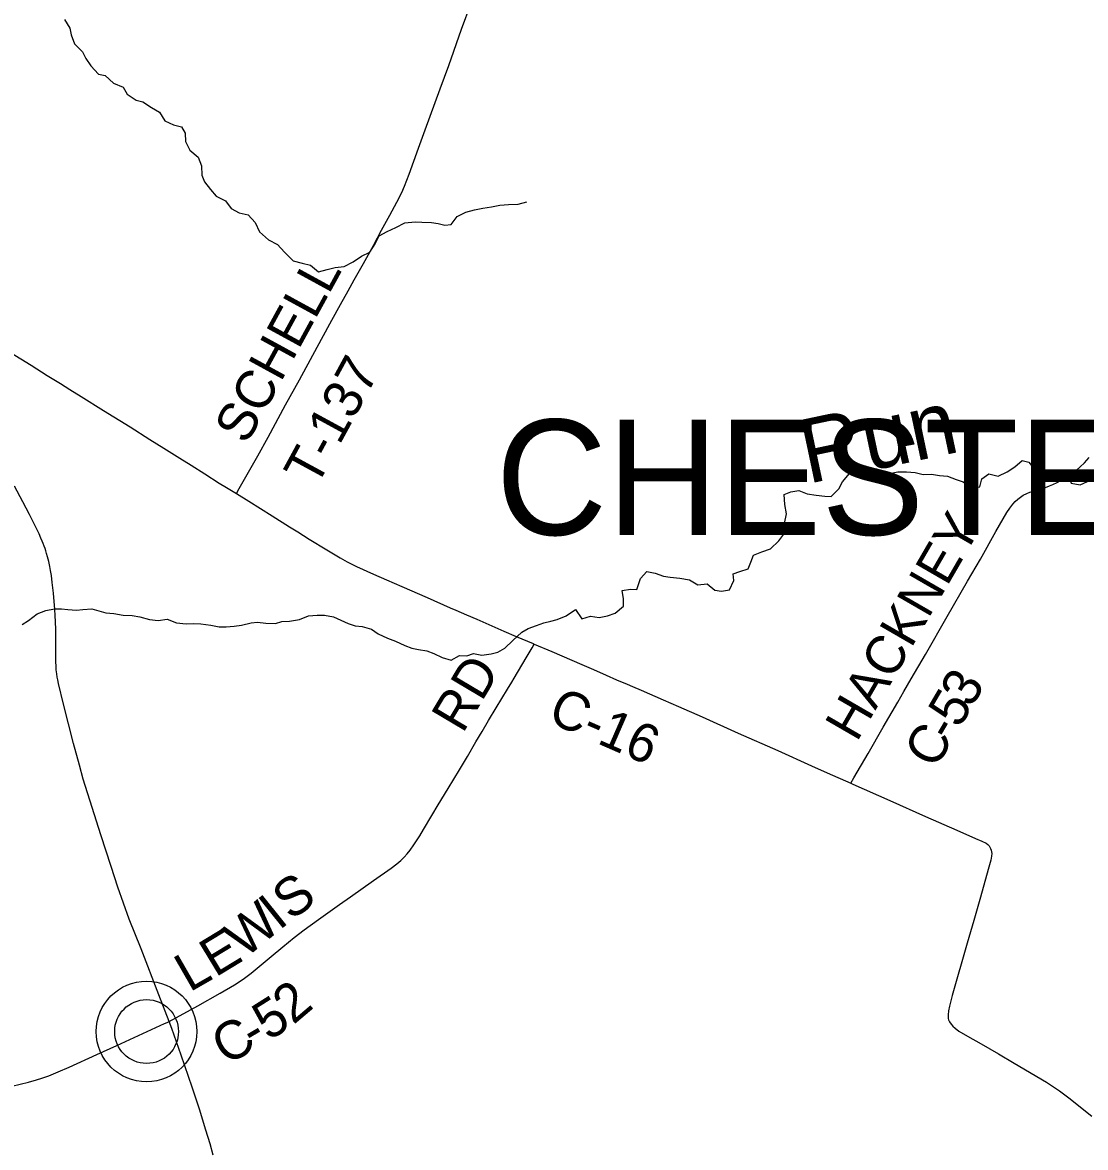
# Model space of a CAD drawing. Extents: x 1442749 to 1756758, y 235267 to 677782.
# Drawn here: x 1560414 to 1568709, y 552520 to 561298 of the extents above; entities that cross this region are included whole.
import ezdxf

# ---------------------------------------------------------------- set-up
doc = ezdxf.new("R2010")
doc.units = 0
for name, color, linetype in [('GM_X_County_Road', 7, 'Continuous'), ('GM_X_County_Road_Text', 7, 'Continuous'), ('GM_X_Minor_River', 7, 'Continuous'), ('GM_X_Minor_River_Text', 7, 'Continuous'), ('GM_X_State_Route', 7, 'Continuous'), ('GM_X_Township_Road', 7, 'Continuous'), ('GM_X_Township_Road_Text', 7, 'Continuous'), ('GM_X_Township_Text', 7, 'Continuous'), ('GM_X_Unincorporated', 7, 'Continuous'), ('GM_X_Unincorporated_Location', 7, 'Continuous')]:
    doc.layers.add(name, color=color, linetype=linetype)

msp = doc.modelspace()

# ---------------------------------------------------------------- linework, layer by layer
at = {"layer": 'GM_X_County_Road'}
for points in [[(1559644.9, 559141.5), (1559858.5, 559011.6), (1559997.1, 558924), (1560206.4, 558794.6), (1560320.7, 558723.8), (1560482.5, 558623.7), (1560607.3, 558544.8), (1560710.3, 558480.9), (1560782.6, 558435.8), (1560871.4, 558379.8), (1561046.9, 558270.7), (1561253.1, 558142.9), (1561408.2, 558044.6), (1561516.6, 557976.6), (1561642, 557898.8), (1561731.1, 557843.3), (1561836.3, 557776.5), (1561949.5, 557703.9), (1562005.6, 557669.8), (1562083.2, 557622.2)], [(1566877, 555363), (1566901.9, 555405.2), (1567013.3, 555594.3), (1567131.1, 555799.1), (1567244.3, 555995), (1567292.2, 556077.2), (1567349.4, 556176.8), (1567460.1, 556366.7), (1567629.7, 556662.8), (1567789.2, 556938), (1567889.4, 557111.3), (1568010.5, 557325.4), (1568095.7, 557473.5), (1568118.8, 557509.6), (1568141.1, 557538.6), (1568161, 557560.9), (1568180.5, 557579.2), (1568201.5, 557595.6), (1568224.2, 557609.7), (1568251.1, 557623), (1568276, 557632.6), (1568338.9, 557652.1), (1568398.1, 557670.6), (1568428.7, 557681.8), (1568455.7, 557693), (1568487.9, 557708.5), (1568530.9, 557731.9), (1568564.6, 557751.7), (1568605.3, 557778.9), (1568636.5, 557802.5), (1568668.6, 557830), (1568701, 557862.1), (1568737.9, 557903.4)], [(1562083.2, 557622.2), (1562181.7, 557561.9), (1562270.9, 557506.7), (1562362.1, 557448.4), (1562497.8, 557362.5), (1562561.8, 557322.6), (1562651.1, 557267.4), (1562787.9, 557183.5), (1562891.9, 557120.8), (1562946.5, 557090.4), (1563020, 557053.6), (1563154.3, 556992.4), (1563253.5, 556949.1), (1563374, 556897.3), (1563572.4, 556810.7), (1563752.8, 556731.8), (1563795.1, 556713.9), (1563879.2, 556677.4), (1563960, 556641.3), (1564170.5, 556549.4), (1564266.9, 556507.6), (1564399.8, 556451.8), (1564407.6, 556448.5)], [(1561559.1, 553502.2), (1561782.9, 553625.7), (1561957.4, 553723.7), (1562067.6, 553788.3), (1562098.1, 553807.5), (1562146.2, 553841.3), (1562198.4, 553880.7), (1562246.7, 553920), (1562354.9, 554010.4), (1562445.3, 554086.6), (1562534.7, 554158.8), (1562613.1, 554218.6), (1562724.7, 554299.6), (1562887.7, 554415.7), (1562973.2, 554476.7), (1563153.1, 554603.2), (1563290.1, 554699.2), (1563334.5, 554732.6), (1563366.9, 554759.9), (1563392.7, 554784.6), (1563416.9, 554810.9), (1563439.2, 554838.9), (1563469.1, 554881.7), (1563515.8, 554952.9), (1563544.6, 555000.5), (1563609.4, 555110.6), (1563657.8, 555192.5), (1563734.8, 555322.2), (1563823.6, 555467.8), (1563885.9, 555571.8), (1563952.4, 555684.7), (1564000.9, 555766.6), (1564051.8, 555851), (1564111, 555949.3), (1564199, 556095.3), (1564232.2, 556151.8), (1564250.6, 556182.9), (1564343.9, 556341.1), (1564390.8, 556420), (1564407.6, 556448.5)], [(1564407.6, 556448.5), (1564544.6, 556390.2), (1564779.4, 556288.7), (1564869.5, 556249.3), (1564968.7, 556206), (1565049.7, 556170.2), (1565134, 556134), (1565173.4, 556117.5), (1565242.8, 556088.1), (1565413.6, 556012.4), (1565533.8, 555959.7), (1565717, 555879.1), (1565998.4, 555753.2), (1566307.4, 555616.6), (1566570.8, 555498.4), (1566693.7, 555443.8), (1566877, 555363)], [(1566877, 555363), (1566894.8, 555355.1), (1567182.4, 555226.8), (1567461.3, 555103.2), (1567705, 554997.1), (1567852, 554931.9), (1567899.8, 554910), (1567933, 554893.6), (1567946.1, 554882.9), (1567956.4, 554873.7), (1567963.6, 554864), (1567969.2, 554851.9), (1567973.9, 554840.6), (1567976.4, 554827), (1567977.4, 554813.5), (1567975.9, 554792.9), (1567970.7, 554761.1), (1567956.2, 554707.5), (1567883.6, 554455.3), (1567837.2, 554291.1), (1567786.8, 554114.4), (1567668.9, 553704.5), (1567646.9, 553621.7), (1567640.6, 553585.6), (1567636.9, 553555.6), (1567636.9, 553542.8), (1567639, 553527.3), (1567641.6, 553515.1), (1567648, 553501.2), (1567661.5, 553481.8), (1567674.1, 553466), (1567691.2, 553449.7), (1567721, 553428.3), (1567789.3, 553388), (1567894.9, 553328), (1568031.3, 553249.6), (1568153, 553178.2), (1568403.8, 553028.9), (1568459.3, 552994.2), (1568507.8, 552960.9), (1568578.2, 552907.6), (1568757.9, 552764.6)], [(1560330, 552997.5), (1560460.3, 553030.5), (1560523.6, 553047.3), (1560564.1, 553059.9), (1560619.5, 553079.6), (1560692.4, 553108.8), (1560779.6, 553146.7), (1560994.6, 553244.4), (1561149.7, 553315.3), (1561522.1, 553487), (1561543.7, 553495.9), (1561559.1, 553502.2)]]:
    msp.add_lwpolyline(points, dxfattribs=at)
at = {"layer": 'GM_X_Minor_River'}
for points in [[(1560742.1, 561321.1), (1560782.8, 561254.1), (1560793.8, 561201.8), (1560820.5, 561131.1), (1560881.4, 561069.7), (1560908.4, 561017), (1560947.4, 560960.1), (1561008.2, 560894.8), (1561060.2, 560883.7), (1561123.1, 560824.3), (1561198.7, 560792.7), (1561229.7, 560737.9), (1561300.9, 560692.4), (1561352.8, 560679.4)], [(1561352.8, 560679.4), (1561420.1, 560633.9), (1561483.5, 560598.6), (1561524.3, 560531.6), (1561593.8, 560500.1), (1561655.7, 560484.8), (1561682.7, 560434.2), (1561685.5, 560370), (1561720.2, 560301.1), (1561785.3, 560247.7), (1561810, 560179), (1561814.6, 560106.8), (1561835.6, 560054.2), (1561880.5, 559995.2), (1561925.6, 559942.1), (1561999, 559906.6), (1562042, 559847.6), (1562105.5, 559814.2), (1562175.3, 559798.8), (1562230.2, 559737.5), (1562264.9, 559664.7), (1562333.8, 559603.2), (1562403.2, 559565.7), (1562458.2, 559506.4), (1562527, 559438.9), (1562596.8, 559419.4), (1562662.7, 559404.1), (1562723.8, 559352.8), (1562792.3, 559371.4), (1562854.8, 559386.2), (1562925.1, 559394.8), (1562994, 559431.6), (1563059, 559474.4), (1563125.8, 559507.1), (1563167.2, 559570.5), (1563196.5, 559634), (1563259.3, 559666.9), (1563328.2, 559699.6), (1563397.1, 559736.3), (1563479.4, 559742.7), (1563531.5, 559741.6), (1563605.6, 559738.2), (1563657.5, 559729.1), (1563709.5, 559718), (1563759.7, 559723), (1563807, 559784.2), (1563873.9, 559819), (1563942.4, 559837.7), (1564006.8, 559850.4), (1564073.1, 559859.1), (1564139.6, 559871.8), (1564205.8, 559878.5), (1564282.1, 559881), (1564348.6, 559899.8)], [(1565103.9, 556744.8), (1565105, 556800.9), (1565094.2, 556865.3), (1565158.6, 556876), (1565208.7, 556875), (1565236.4, 556958.7), (1565285.6, 557013.8), (1565351.6, 557002.5), (1565417.2, 556977.1), (1565469.2, 556970.1), (1565543.2, 556962.6), (1565619.2, 556949), (1565684.6, 556911.6), (1565756.9, 556918.2), (1565818, 556868.9), (1565870, 556861.8), (1565932.4, 556870.6), (1565965.9, 556944.1), (1565960.9, 556996.3), (1566011.4, 557013.4), (1566075.9, 557034.1), (1566099.1, 557087.8), (1566118.2, 557141.6), (1566182.9, 557168.3), (1566251.5, 557191), (1566316.9, 557253.9), (1566362.2, 557317.1), (1566361.7, 557389.3), (1566375.2, 557465.2), (1566362.6, 557537.7), (1566358.1, 557614), (1566408.7, 557635), (1566473, 557645.7), (1566538.7, 557620.4), (1566608.7, 557611), (1566674.6, 557601.6), (1566724.7, 557600.6), (1566784.1, 557659.6), (1566813.2, 557713.1), (1566866.6, 557778.2), (1566936.7, 557776.8), (1567007.3, 557797.5), (1567059, 557774.4), (1567127.1, 557773), (1567179.3, 557778), (1567243.8, 557790.8), (1567311.9, 557791.4), (1567380, 557786), (1567443.8, 557770.7), (1567508, 557773.4), (1567570, 557764.2), (1567632, 557758.9), (1567699.7, 557733.5), (1567753.5, 557714.4), (1567816.7, 557667), (1567885, 557675.7), (1567900.3, 557737.5), (1567955.2, 557776.6), (1568027, 557759.1), (1568097.8, 557791.8), (1568156.7, 557830.7), (1568215.8, 557879.6), (1568267.7, 557868.6), (1568326.4, 557793.2), (1568393.7, 557751.8), (1568472.3, 557774.2), (1568523, 557799.3), (1568580.5, 557770.1), (1568597.2, 557703.6), (1568669.1, 557690.1), (1568723.8, 557717.1)], [(1560411.5, 556601.9), (1560462.3, 556633), (1560527.4, 556683.8), (1560596.1, 556710.5), (1560664.6, 556723.2), (1560718.7, 556724.1), (1560768.7, 556719.1), (1560834.7, 556711.8), (1560885, 556716.8), (1560955.3, 556723.4), (1561011.1, 556708.3), (1561064.9, 556691.2), (1561127, 556687.9), (1561198.9, 556674.4), (1561269, 556671), (1561330.9, 556659.8), (1561404.7, 556640.3), (1561472.7, 556632.9), (1561543.1, 556641.5), (1561616.7, 556614), (1561690.7, 556606.5), (1561748.9, 556609.3), (1561807, 556606.2), (1561885, 556594.6), (1561948.9, 556583.3), (1562003, 556582.2), (1562065.3, 556587), (1562123.6, 556595.8), (1562198.1, 556614.4), (1562248.4, 556619.4), (1562312.4, 556612.1), (1562388.5, 556608.6), (1562438.9, 556623.6), (1562497.1, 556626.5), (1562575.6, 556640.9), (1562646.3, 556667.6), (1562714.6, 556674.3), (1562770.7, 556673.1), (1562840.6, 556659.7), (1562898.3, 556634.5), (1562955.9, 556609.3), (1563009.7, 556590.2), (1563065.7, 556585), (1563137.4, 556563.6), (1563190.9, 556528.4), (1563262.4, 556494.9), (1563324.1, 556471.6), (1563397.6, 556438.1), (1563451.3, 556416.9), (1563505.2, 556405.8), (1563569.2, 556394.5), (1563622.9, 556373.4), (1563688.4, 556344), (1563758.2, 556322.6), (1563825.1, 556359.3), (1563881.2, 556356.2), (1563933.7, 556375.2), (1563999.6, 556361.9), (1564071.9, 556372.4), (1564124.3, 556385.4), (1564177.1, 556416.5), (1564240.4, 556475.3), (1564309.9, 556540.1), (1564360.6, 556569.2), (1564425.2, 556591.9), (1564481.7, 556612.9), (1564536.1, 556625.8), (1564586.5, 556640.8), (1564657.3, 556669.5), (1564728.4, 556718.2), (1564779.1, 556645), (1564847.7, 556665.7), (1564913.6, 556656.4), (1564978.1, 556669.1), (1565038.6, 556688), (1565103.9, 556744.8)]]:
    msp.add_lwpolyline(points, dxfattribs=at)
at = {"layer": 'GM_X_State_Route'}
msp.add_lwpolyline([(1561903.1, 552460.9), (1561877.7, 552549.1), (1561846.1, 552655.9), (1561794.5, 552818.3), (1561737.8, 552989.5), (1561651.4, 553240.4), (1561579.8, 553448.1), (1561559.1, 553502.2), (1561478.8, 553711.4), (1561339.7, 554069.2), (1561247.2, 554300.7), (1561157, 554550.6), (1561105.3, 554713.2), (1561026.1, 554959.9), (1560958.5, 555172.5), (1560888.7, 555394.8), (1560858.2, 555502), (1560810.9, 555672.5), (1560734.9, 555978.1), (1560696.3, 556139.5), (1560690.6, 556168.7), (1560686, 556188.7), (1560682, 556215.6), (1560678, 556247.6), (1560675.7, 556272.8), (1560674, 556311.7), (1560673.7, 556350.4), (1560674.2, 556468.8), (1560674.2, 556562.9), (1560672.3, 556620.7), (1560670, 556671.1), (1560667.2, 556718), (1560655.7, 556845.6), (1560646.6, 556928.6), (1560639.7, 556982.9), (1560633.3, 557021.9), (1560627.6, 557054.5), (1560619.4, 557093.1), (1560610.3, 557127.8), (1560602.5, 557155.6), (1560596.8, 557175.6), (1560591.2, 557192.9), (1560583.4, 557213.3), (1560575, 557233.8), (1560567.7, 557251.9), (1560557.7, 557275.4), (1560543.9, 557307.1), (1560530.4, 557335.6), (1560468.4, 557458.4), (1560416.5, 557556.9), (1560350.7, 557681.3)], dxfattribs=at)
at = {"layer": 'GM_X_Township_Road'}
msp.add_lwpolyline([(1562083.2, 557622.2), (1562105, 557661.7), (1562250.7, 557917.5), (1562330.6, 558063.4), (1562467.1, 558316.2), (1562574.9, 558510.7), (1562747.2, 558828.1), (1562827.6, 558974.8), (1562896.8, 559097.5), (1562956.1, 559204), (1563003.3, 559289.6), (1563074.7, 559418.7), (1563152.1, 559559.4), (1563215.8, 559677.9), (1563280.9, 559795.6), (1563335.6, 559896.2), (1563374.1, 559971.4), (1563396.1, 560021.6), (1563432, 560114.1), (1563505.7, 560318), (1563555.7, 560460.3), (1563672.9, 560780.6), (1563740.5, 560961.9), (1563840.1, 561246.7), (1563914.9, 561449.9)], dxfattribs=at)
at = {"layer": 'GM_X_Unincorporated'}
for radius in [392.8, 249]:
    msp.add_circle((1561382.5, 553424.3), radius, dxfattribs=at)
at = {"layer": 'GM_X_Unincorporated_Location'}
msp.add_line((1561382.5, 553424.3), (1561382.5, 553424.3), dxfattribs=at)

# ---------------------------------------------------------------- texts
at = {"layer": 'GM_X_County_Road_Text'}
for s, rotation, p in [('HACKNEY', 59.94395, (1566924.5, 555676.7)), ('RD', 59.28607, (1563849.4, 555743.4)), ('3', 59.79463, (1567818.4, 555942.7)), ('C-16', 336.45053, (1564501.3, 555846.4)), ('5', 59.66322, (1567724.7, 555782.6)), ('C', 59.61826, (1567537.7, 555463.5)), ('-', 59.62677, (1567662.3, 555676.1)), ('S', 36.81335, (1562510.2, 554284.4)), ('I', 38.68906, (1562416.1, 554209)), ('W', 39.59724, (1562149.3, 553988.2)), ('E', 31.28104, (1561918.8, 553844.1)), ('L', 29.9171, (1561717.6, 553728.2)), ('2', 40.21126, (1562527.2, 553473.1)), ('5', 32.26049, (1562334.3, 553347.7)), ('C', 30.15347, (1562004.6, 553155.4)), ('-', 30.32576, (1562218.5, 553279.7))]:
    msp.add_text(s, height=300, rotation=rotation, dxfattribs=at).set_placement(p)
at = {"layer": 'GM_X_Minor_River_Text'}
msp.add_text('Run', height=500, rotation=11.94249, dxfattribs=at).set_placement((1566542, 557697.4))
at = {"layer": 'GM_X_Township_Road_Text'}
for s, rotation, p in [('SCHELL', 61.3311, (1562161.9, 557996.6)), ('T-137', 61.45639, (1562706, 557661.8))]:
    msp.add_text(s, height=300, rotation=rotation, dxfattribs=at).set_placement(p)
at = {"layer": 'GM_X_Township_Text'}
msp.add_text('CHESTER', height=900, rotation=0.00001, dxfattribs=at).set_placement((1564107.2, 557299.9))

doc.saveas('drawing.dxf')
